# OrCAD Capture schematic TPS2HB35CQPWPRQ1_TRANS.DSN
size C; title: TPS2HB35CQPWPRQ1: 40-V, 35-mÙ Dual-Channel Smart; rev: 1.0; note: Datasheet: SLVSDZ4D        EVM: SLVUBD4B; note: High-Side Switch
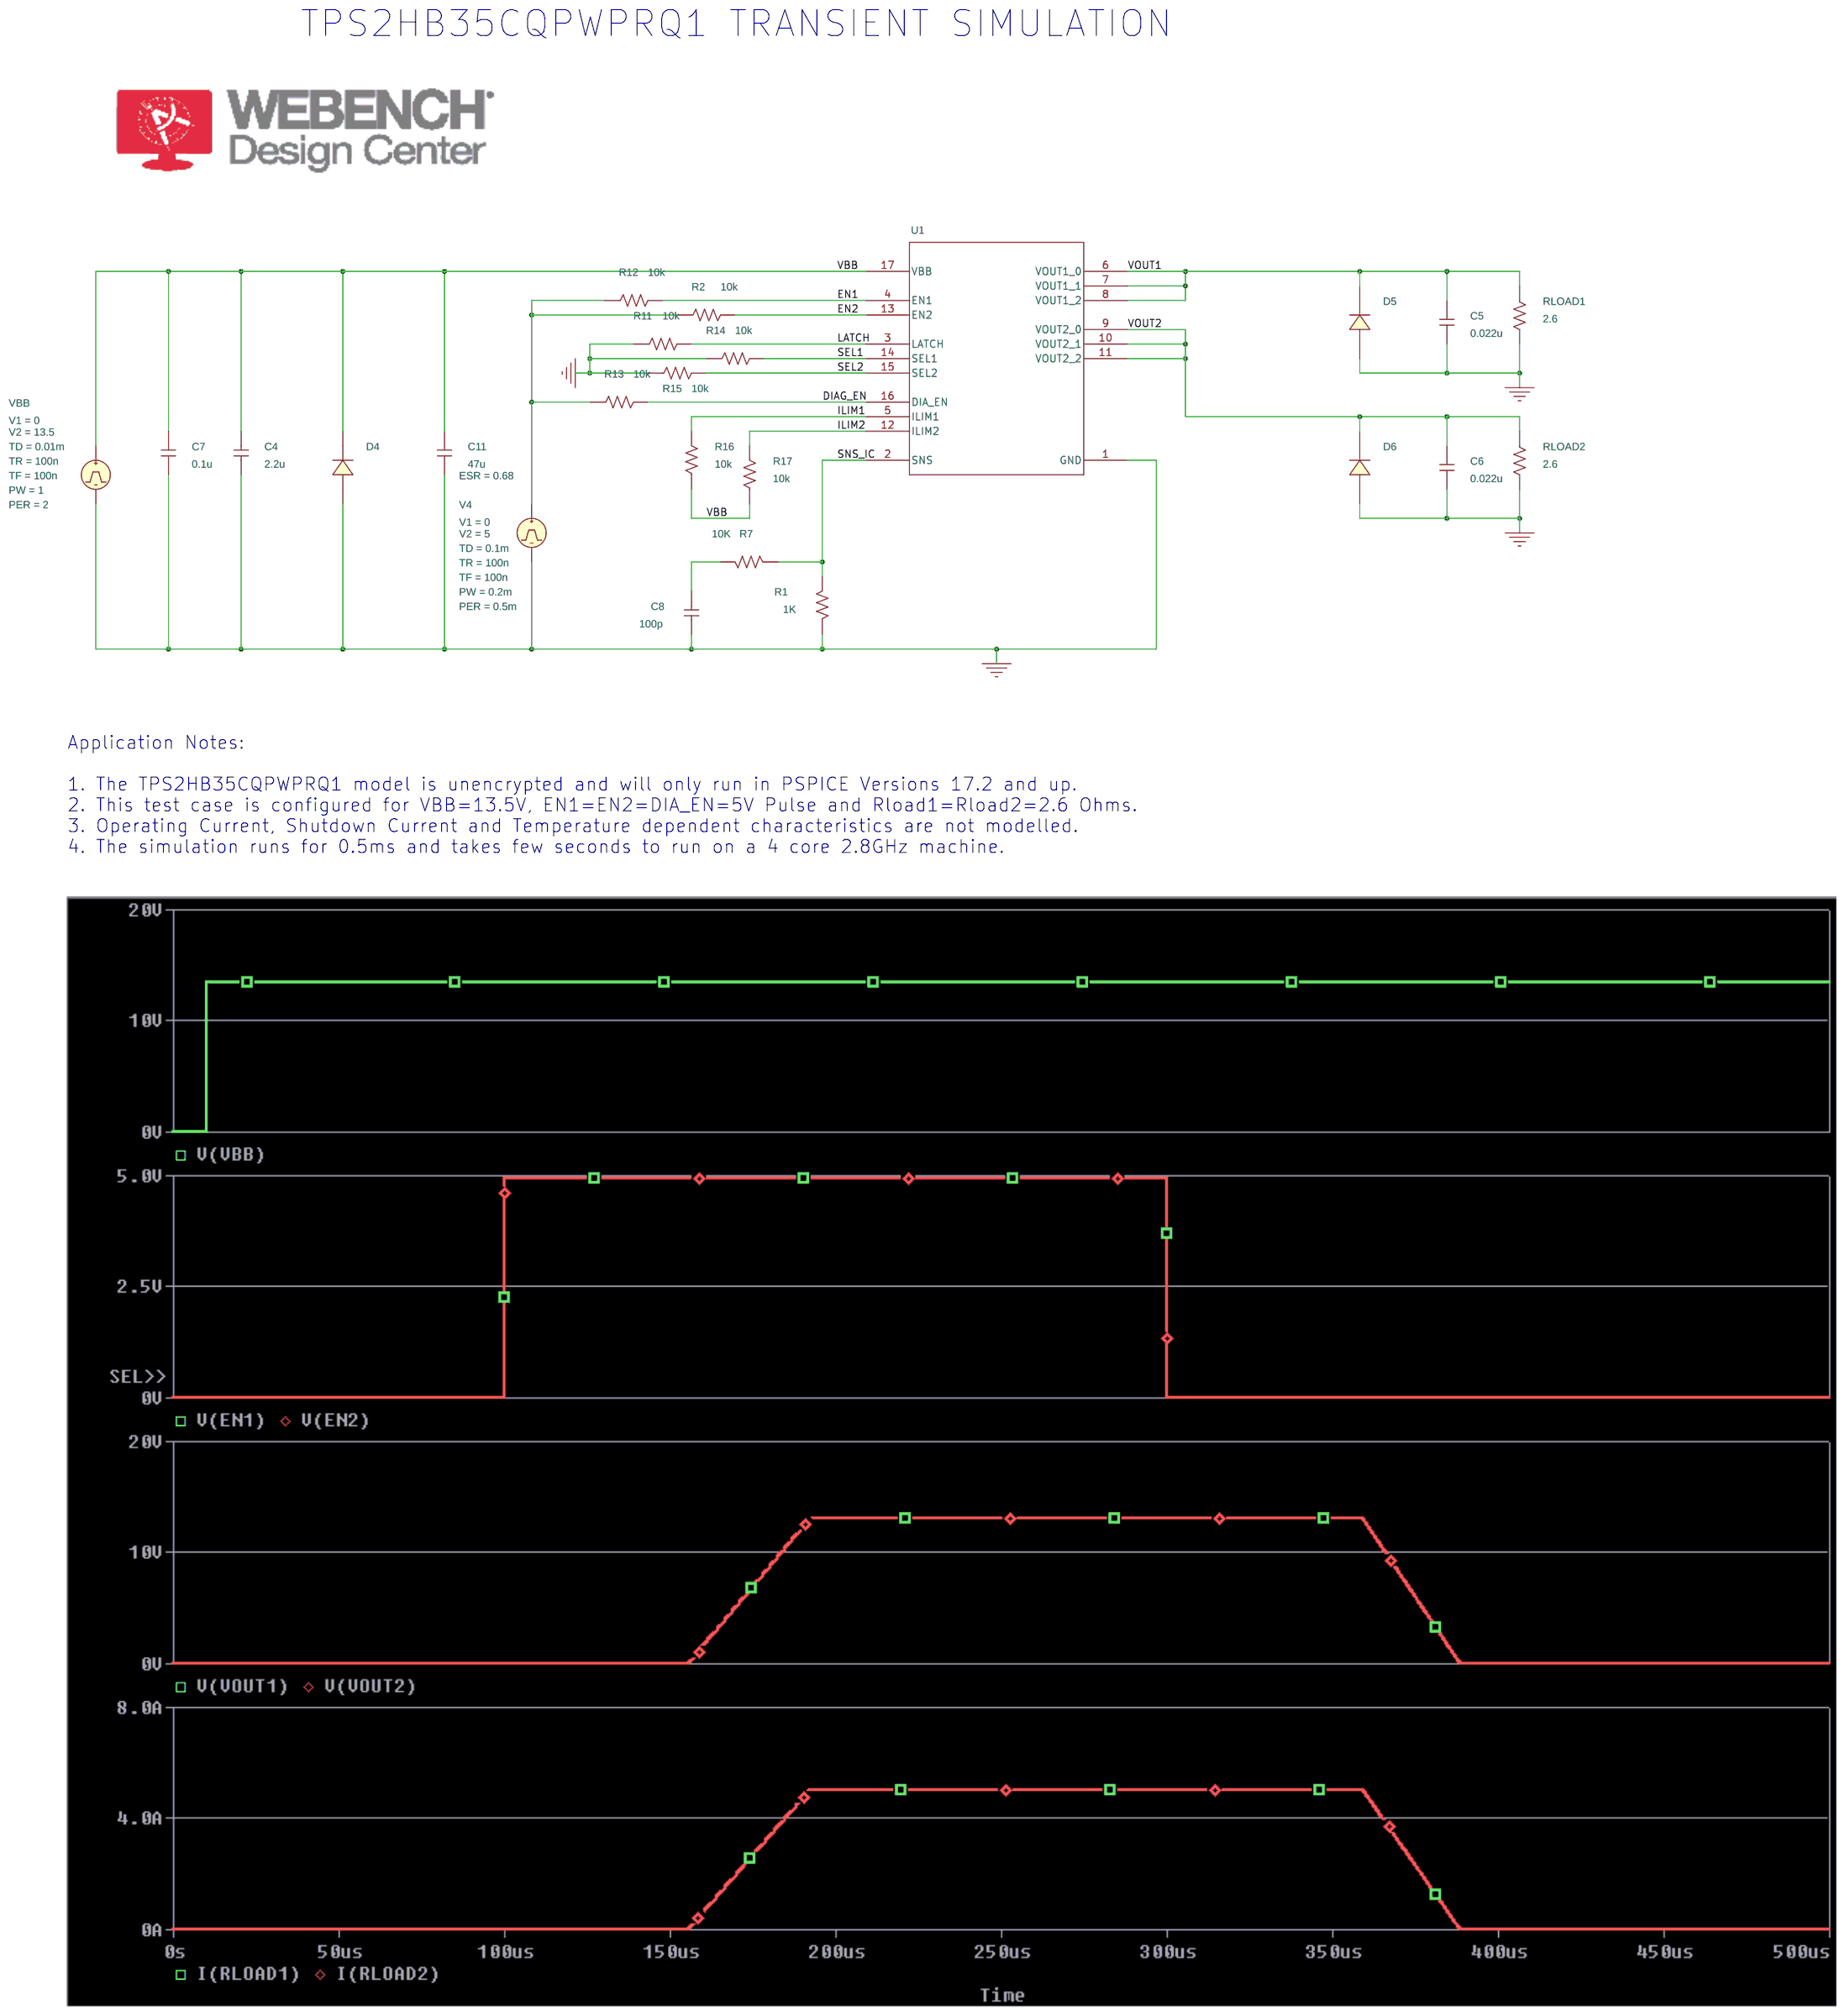
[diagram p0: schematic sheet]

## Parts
C4  2.2u  [RAD/CK05]
C5  0.022u  [RAD/CK05]
C6  0.022u  [RAD/CK05]
C7  0.1u  [RAD/CK05]
C8  100p  [RAD/CK05]
C11  47u  [RAD/CK05]
D4  SMCJ33A
D5  SMCJ33A
D6  SMCJ33A
R1  1K  [AX/RC05]
R2  10k  [AX/RC05]
R7  10K  [AX/RC05]
R11  10k  [AX/RC05]
R12  10k  [AX/RC05]
R13  10k  [AX/RC05]
R14  10k  [AX/RC05]
R15  10k  [AX/RC05]
R16  10k  [AX/RC05]
R17  10k  [AX/RC05]
RLOAD1  2.6  [AX/RC05]
RLOAD2  2.6  [AX/RC05]
U1  TPS2HB35C-Q1PWP_TRANS  [PWP0016M-IPC_A]
V4  VPULSE
VBB  VPULSE

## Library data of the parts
C4-C8 = C
C11 = C: AppProp: InductiveSlave:;SRF:;PrevCap:47u;PrevESL:; ESR: 0.68
D4-D6 = D_D1: PSpiceTemplate: D^@REFDES  %1 %2 @MODEL ?AREA/@AREA/
R1 R2 R7 R11-R17 RLOAD1 RLOAD2 = R
U1 = TPS2HB35C-Q1PWP_TRANS
V4 = VPULSE: PER: 0.5m; PW: 0.2m; TD: 0.1m; TF: 100n; TR: 100n; V1: 0; V2: 5
VBB = VPULSE: PER: 2; PW: 1; TD: 0.01m; TF: 100n; TR: 100n; V1: 0; V2: 13.5

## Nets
0: C4.2 C5.2 C6.2 C7.2 C8.2 C11.1 D4.1 D5.1 D6.1 R1.1 R11.1 R14.1 R15.1 RLOAD1.2 RLOAD2.2 U1.1(GND) V4.2(-) VBB.2(-)
DIAG_EN: R13.2 U1.16(DIA_EN)
EN1: R12.2 U1.4(EN1)
EN2: R2.2 U1.13(EN2)
ILIM1: R16.2 U1.5(ILIM1)
ILIM2: R17.2 U1.12(ILIM2)
LATCH: R11.2 U1.3(LATCH)
SEL1: R14.2 U1.14(SEL1)
SEL2: R15.2 U1.15(SEL2)
SNS_IC: R1.2 R7.1 U1.2(SNS)
VBB: C4.1 C7.1 C11.2 D4.2 R16.1 R17.1 U1.17(VBB) VBB.1(+)
VOUT1: C5.1 D5.2 RLOAD1.1 U1.6(VOUT1_0) U1.7(VOUT1_1) U1.8(VOUT1_2)
VOUT2: C6.1 D6.2 RLOAD2.1 U1.9(VOUT2_0) U1.10(VOUT2_1) U1.11(VOUT2_2)
N16847536: R2.1 R12.1 R13.1 V4.1(+)
N16857704: C8.1 R7.2

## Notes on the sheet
- TPS2HB35CQPWPRQ1 TRANSIENT SIMULATION
- Application Notes:
  1. The TPS2HB35CQPWPRQ1 model is unencrypted and will only run in PSPICE Versions 17.2 and up.
  2. This test case is configured for VBB=13.5V, EN1=EN2=DIA_EN=5V Pulse and Rload1=Rload2=2.6 Ohms.
  3. Operating Current, Shutdown Current and Temperature dependent characteristics are not modelled.
  4. The simulation runs for 0.5ms and takes few seconds to run on a 4 core 2.8GHz machine.
